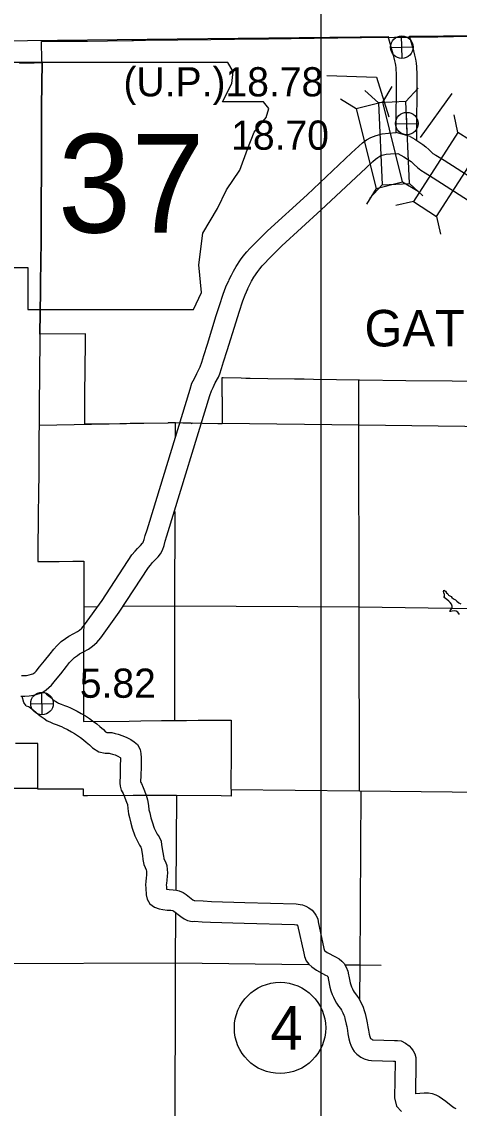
# Model space of a CAD drawing. Extents: x 77230 to 630905, y 790554 to 1662844.
# Drawn here: x 303084 to 315734, y 1607947 to 1639405 of the extents above; entities that cross this region are included whole.
import ezdxf

# ---------------------------------------------------------------- set-up
doc = ezdxf.new("R2010")
doc.units = 0
for name, color, linetype in [('Level 12', 7, 'Continuous'), ('Level 14', 7, 'Continuous'), ('Level 15', 7, 'Continuous'), ('Level 16', 7, 'Continuous'), ('Level 17', 7, 'Continuous'), ('Level 19', 7, 'Continuous'), ('Level 22', 7, 'Continuous'), ('Level 23', 7, 'Continuous'), ('Level 24', 7, 'Continuous'), ('Level 27', 7, 'Continuous'), ('Level 28', 7, 'Continuous'), ('Level 31', 7, 'Continuous'), ('Level 32', 7, 'Continuous'), ('Level 33', 7, 'Continuous'), ('Level 34', 7, 'Continuous')]:
    doc.layers.add(name, color=color, linetype=linetype)

msp = doc.modelspace()

# ---------------------------------------------------------------- linework, layer by layer
at = {"layer": 'Level 12'}
for points in [[(303674, 1638222), (303663, 1638289), (303655, 1638835), (304099, 1638839), (304988, 1638847), (305561, 1638854), (306265, 1638863), (306315, 1638864), (306659, 1638870), (307594, 1638886), (308550, 1638893), (309927, 1638906), (310220, 1638909), (311538, 1638928), (312906, 1638953), (313857, 1638959), (313926, 1638962), (313938, 1638962)], [(313938, 1638962), (314223, 1638962), (315117, 1638972), (315117, 1638973), (315568, 1638978), (316467, 1638989)], [(303015, 1638201), (303347, 1638211)], [(303347, 1638211), (303447, 1638215), (303674, 1638222)], [(303674, 1638222), (303659, 1636961), (303659, 1636870), (303659, 1636795), (303656, 1636178), (303655, 1635806), (303654, 1635691), (303654, 1635609), (303654, 1635319), (303653, 1635258), (303652, 1635080), (303652, 1635003), (303648, 1634240), (303641, 1632966), (303636, 1632540), (303635, 1632427), (303635, 1632414), (303629, 1631897), (303625, 1631611), (303609, 1630362)], [(303609, 1630362), (303625, 1631611), (303629, 1631897), (303635, 1632414), (303635, 1632427), (303636, 1632540), (303641, 1632966), (303648, 1634240), (303652, 1635003), (303652, 1635080), (303653, 1635258), (303654, 1635319), (303654, 1635609), (303654, 1635691), (303655, 1635806), (303656, 1636178), (303659, 1636795), (303659, 1636870), (303659, 1636961), (303674, 1638222)], [(303609, 1630362), (303595, 1629079), (303589, 1628427), (303584, 1627807), (303584, 1627724), (303582, 1627429), (303582, 1627400), (303581, 1627254), (303577, 1626410), (303576, 1626272), (303570, 1625818), (303557, 1625079), (303554, 1624781), (303552, 1624383), (303550, 1623773), (303556, 1623774), (304170, 1623780), (304557, 1623785), (304883, 1623789), (304880, 1623469), (304877, 1622973), (304877, 1622889), (304876, 1622469), (304875, 1622150), (304874, 1621514), (304874, 1621502), (304873, 1621446), (304873, 1621357), (304873, 1621299), (304873, 1621276), (304873, 1621266), (304873, 1621149), (304871, 1620475), (304870, 1619828), (304870, 1619144), (306192, 1619159), (306192, 1619157), (306524, 1619162), (307124, 1619171), (307514, 1619177), (307514, 1619174), (307847, 1619177), (308183, 1619180), (308518, 1619183), (308518, 1619184), (308853, 1619186), (308853, 1619183), (309142, 1619188), (309139, 1618306), (309134, 1617203), (309135, 1617152), (309143, 1617152), (309143, 1617151), (309143, 1616981), (308850, 1616989), (307559, 1616999), (306303, 1616999), (304987, 1616992), (304869, 1616991), (304870, 1617183), (303987, 1617187), (303861, 1617188), (303572, 1617189), (303548, 1617189), (303548, 1617586), (303548, 1617900), (303548, 1618225), (303547, 1618509), (303097, 1618508), (302905, 1618511)], [(318201, 1628963), (315525, 1628994), (314187, 1629010), (312850, 1629028), (311524, 1629048), (311248, 1629052), (310974, 1629056), (310195, 1629067), (309686, 1629076), (309627, 1629077), (309559, 1629078), (309427, 1629081), (308908, 1629096), (308870, 1629097), (308869, 1629097), (308869, 1629093), (308868, 1628548), (308868, 1628543), (308876, 1628542), (308877, 1627917), (308877, 1627760), (308754, 1627763), (308309, 1627773), (308009, 1627779), (308004, 1627760), (307975, 1627780), (307949, 1627784), (307947, 1627781), (307922, 1627781), (307738, 1627785), (307532, 1627790), (307314, 1627788), (307309, 1627787), (306219, 1627773), (305916, 1627768), (304904, 1627750), (304908, 1628383), (304911, 1628711), (304911, 1628866), (304914, 1629102), (304926, 1630366), (303609, 1630362)]]:
    msp.add_lwpolyline(points, dxfattribs=at)
at = {"layer": 'Level 14'}
for points in [[(314296, 1638984), (318235, 1639028), (323522, 1639077), (328068, 1639116), (330690, 1639138)], [(293947, 1638752), (297089, 1638789), (302369, 1638852), (307582, 1638906), (312865, 1638969), (313674, 1638978)]]:
    msp.add_lwpolyline(points, dxfattribs=at)
at = {"layer": 'Level 15'}
for points in [[(301883, 1617216), (302239, 1617216), (303548, 1617210)], [(309134, 1617173), (312849, 1617136), (317311, 1617093)]]:
    msp.add_lwpolyline(points, dxfattribs=at)
at = {"layer": 'Level 16'}
for points in [[(312849, 1617136), (312844, 1622477), (312834, 1627745), (312830, 1629028)], [(303600, 1627720), (306611, 1627778)], [(307516, 1627790), (307516, 1627774), (307515, 1627357)], [(308877, 1627782), (312836, 1627739), (318179, 1627668), (323444, 1627634)], [(307511, 1625228), (307505, 1622474), (307501, 1619177)], [(304876, 1622468), (305278, 1622472)], [(306029, 1622481), (307509, 1622496), (312844, 1622467), (318160, 1622388), (323421, 1622343)], [(307559, 1616999), (307538, 1614269)], [(312856, 1611101), (312866, 1612102), (312895, 1617136)], [(307533, 1613613), (307521, 1612141), (307506, 1606820)], [(294244, 1612117), (296783, 1612127), (302206, 1612135), (307527, 1612156), (311375, 1612114)], [(312444, 1612103), (312868, 1612098), (313480, 1612091)]]:
    msp.add_lwpolyline(points, dxfattribs=at)
at = {"layer": 'Level 17'}
for points in [[(315462, 1622329), (315474, 1622349), (315494, 1622380), (315511, 1622404), (315527, 1622442), (315526, 1622488), (315506, 1622540), (315471, 1622588), (315433, 1622629), (315375, 1622675), (315340, 1622708), (315302, 1622732), (315292, 1622738), (315308, 1622768), (315305, 1622822), (315291, 1622868), (315280, 1622908), (315292, 1622944), (315332, 1622916), (315363, 1622875), (315401, 1622839), (315423, 1622803), (315499, 1622760), (315524, 1622736), (315570, 1622699), (315626, 1622663), (315662, 1622626), (315719, 1622584), (315781, 1622553)], [(315744, 1622244), (315692, 1622306), (315640, 1622341), (315600, 1622349), (315532, 1622342), (315494, 1622332), (315462, 1622329)]]:
    msp.add_lwpolyline(points, dxfattribs=at)
at = {"layer": 'Level 19'}
for p, q in [((313525, 1637077), (313797, 1637529)), ((314188, 1637095), (314544, 1637485)), ((312756, 1636886), (312304, 1637159)), ((313397, 1637059), (313007, 1637415)), ((315696, 1636198), (315584, 1636714)), ((313504, 1634686), (313148, 1634296)), ((314096, 1634770), (314548, 1634498)), ((314295, 1634721), (314685, 1634365)), ((313327, 1634580), (313054, 1634128)), ((314412, 1634199), (313896, 1634087)), ((315078, 1633771), (315191, 1633255))]:
    msp.add_line(p, q, dxfattribs=at)
for points in [[(314096, 1634770), (313525, 1637077), (312756, 1636886), (313327, 1634580)], [(313397, 1637059), (313504, 1634686), (314295, 1634721), (314188, 1637095)], [(315078, 1633771), (316363, 1635770), (315696, 1636198), (314412, 1634199)]]:
    msp.add_lwpolyline(points, close=True, dxfattribs=at)
at = {"layer": 'Level 22'}
for points in [[(313911, 1636194), (313916, 1637858), (313905, 1638071), (313901, 1638143), (313893, 1638195), (313871, 1638277), (313838, 1638400), (313674, 1638978)], [(314510, 1635963), (314516, 1637873), (314504, 1638103), (314498, 1638204), (314481, 1638319), (314450, 1638433), (314417, 1638559), (314296, 1638984)], [(303207, 1619603), (303142, 1619697), (303092, 1619871)], [(303712, 1620010), (303803, 1619937), (303890, 1619865), (303984, 1619783), (304070, 1619724), (304113, 1619695), (304147, 1619680), (304221, 1619647), (304318, 1619611), (304410, 1619577), (304489, 1619539), (304571, 1619500), (304685, 1619441), (304805, 1619377), (304926, 1619313), (305038, 1619234), (305134, 1619168), (305251, 1619080), (305338, 1619001), (305450, 1618913), (305510, 1618850), (305544, 1618829), (305564, 1618824), (305685, 1618825), (305783, 1618801), (305874, 1618780), (306010, 1618732), (306126, 1618678), (306239, 1618619), (306330, 1618555), (306429, 1618476), (306503, 1618336), (306531, 1618215), (306541, 1618092), (306532, 1617830), (306526, 1617585), (306522, 1617401), (306525, 1617379), (306547, 1617345), (306592, 1617238), (306680, 1617008), (306723, 1616879), (306748, 1616708), (306763, 1616584), (306784, 1616500), (306816, 1616355), (306852, 1616238), (306912, 1616061), (306968, 1615944), (306997, 1615885), (307056, 1615808), (307113, 1615678), (307125, 1615571), (307165, 1615353), (307179, 1615243), (307190, 1615186), (307196, 1615173), (307244, 1615078), (307276, 1614973), (307289, 1614863), (307294, 1614760), (307290, 1614664), (307282, 1614552), (307267, 1614450), (307264, 1614414), (307269, 1614354), (307272, 1614292), (307350, 1614282), (307465, 1614275), (307561, 1614259), (307637, 1614242), (307748, 1614196), (307837, 1614137), (308032, 1613982), (308066, 1613960), (308084, 1613961), (308334, 1613948), (308568, 1613937), (309532, 1613908)], [(303207, 1619603), (303283, 1619577), (303298, 1619571), (303333, 1619544), (303425, 1619471), (303503, 1619407), (303614, 1619310), (303733, 1619227), (303822, 1619169), (303900, 1619133), (303994, 1619091), (304110, 1619048), (304177, 1619023), (304230, 1618998), (304305, 1618962), (304407, 1618910), (304523, 1618848), (304611, 1618801), (304695, 1618742), (304784, 1618681), (304867, 1618618), (304950, 1618542), (305046, 1618467), (305130, 1618379), (305309, 1618269), (305493, 1618224), (305615, 1618225), (305645, 1618217), (305707, 1618203), (305782, 1618177), (305858, 1618141), (305926, 1618105), (305938, 1618096), (305940, 1618078), (305932, 1617847), (305926, 1617599), (305921, 1617363), (305934, 1617276), (305956, 1617153), (306015, 1617063), (306035, 1617015), (306114, 1616806), (306137, 1616739), (306153, 1616627), (306172, 1616474), (306200, 1616363), (306235, 1616203), (306281, 1616053), (306356, 1615834), (306429, 1615681), (306485, 1615568), (306528, 1615511), (306532, 1615483), (306572, 1615261), (306587, 1615147), (306613, 1615009), (306652, 1614918), (306685, 1614853), (306686, 1614850), (306690, 1614812), (306694, 1614756), (306691, 1614700), (306685, 1614619), (306670, 1614517), (306662, 1614412), (306670, 1614316), (306678, 1614125), (306707, 1614003), (306785, 1613869), (306921, 1613768), (307053, 1613724), (307166, 1613700), (307293, 1613685), (307397, 1613678), (307445, 1613670), (307453, 1613668), (307466, 1613663), (307485, 1613650), (307680, 1613496), (307781, 1613429), (307881, 1613382), (308016, 1613357), (308083, 1613360), (308305, 1613348), (308546, 1613338), (309514, 1613308)], [(309531, 1613908), (311020, 1613866), (311134, 1613850), (311205, 1613834), (311295, 1613802), (311385, 1613753), (311481, 1613680), (311548, 1613598), (311587, 1613540), (311643, 1613433), (311652, 1613345), (311823, 1612569), (311835, 1612519), (311847, 1612508), (311915, 1612461), (312155, 1612332), (312263, 1612271), (312334, 1612208), (312409, 1612134), (312467, 1612033), (312517, 1611915), (312536, 1611814), (312543, 1611770), (312581, 1611583), (312596, 1611524), (312618, 1611465), (312644, 1611402), (312665, 1611358), (312692, 1611313), (312733, 1611256), (312781, 1611189), (312838, 1611112), (312880, 1611033), (312915, 1610956), (312951, 1610874), (312986, 1610780), (313010, 1610687), (313050, 1610513), (313069, 1610423), (313090, 1610300), (313107, 1610204), (313127, 1610096), (313146, 1610026), (313158, 1609991), (313168, 1609968), (313168, 1609968), (313170, 1609966), (313203, 1609943), (313225, 1609931), (313243, 1609925), (313244, 1609925), (313864, 1609913), (313944, 1609907), (314058, 1609896), (314184, 1609834), (314290, 1609759), (314352, 1609678), (314404, 1609611), (314448, 1609519), (314475, 1609419), (314483, 1609319), (314482, 1609282)], [(309514, 1613308), (310971, 1613267), (311025, 1613260), (311037, 1613257), (311048, 1613253), (311058, 1613248), (311059, 1613247), (311238, 1612434), (311261, 1612341), (311303, 1612217), (311388, 1612115), (311473, 1612037), (311602, 1611948), (311866, 1611805), (311914, 1611779), (311924, 1611770), (311928, 1611766), (311939, 1611741), (311945, 1611706), (311954, 1611658), (311995, 1611453), (312022, 1611344), (312061, 1611243), (312096, 1611159), (312135, 1611075), (312189, 1610985), (312245, 1610906), (312297, 1610834), (312329, 1610791), (312340, 1610770), (312366, 1610712), (312395, 1610647), (312413, 1610600), (312426, 1610546), (312464, 1610385), (312479, 1610311), (312499, 1610197), (312516, 1610098), (312542, 1609961), (312572, 1609852), (312597, 1609775), (312644, 1609670), (312700, 1609591), (312771, 1609513), (312890, 1609430), (312988, 1609378), (313110, 1609337), (313201, 1609326), (313834, 1609314), (313877, 1609310), (313882, 1609304), (313882, 1609299)], [(313882, 1609295), (313866, 1608251)], [(314482, 1609286), (314468, 1608369)], [(313866, 1608251), (313917, 1608003), (314060, 1607855)], [(314477, 1608377), (314593, 1608387), (314723, 1608395), (314841, 1608391), (314954, 1608378), (315061, 1608340), (315153, 1608288), (315343, 1608154), (315549, 1607991), (315601, 1607956), (315631, 1607941)]]:
    msp.add_lwpolyline(points, dxfattribs=at)
at = {"layer": 'Level 23'}
for points in [[(309072, 1631920), (309144, 1632071), (309210, 1632187), (309286, 1632321), (309412, 1632509), (309488, 1632618), (309590, 1632741), (309680, 1632835), (309781, 1632946), (310015, 1633180), (310188, 1633354), (311333, 1634398), (312619, 1635607), (312829, 1635804), (312935, 1635900), (313053, 1635982), (313177, 1636054), (313327, 1636113), (313501, 1636156), (313686, 1636183), (313911, 1636194)], [(314310, 1636085), (313911, 1636194)], [(314310, 1636085), (314445, 1636001), (314681, 1635853), (314769, 1635786), (314851, 1635703), (314922, 1635636), (314974, 1635593), (315058, 1635541), (315294, 1635401), (317823, 1633776)], [(309614, 1631663), (309676, 1631793), (309731, 1631890), (309797, 1632005), (309908, 1632171), (309966, 1632255), (310038, 1632341), (310118, 1632425), (310215, 1632531), (310440, 1632757), (310603, 1632921), (311741, 1633958), (313030, 1635169), (313236, 1635363), (313309, 1635429), (313376, 1635476), (313440, 1635513), (313509, 1635540), (313617, 1635567), (313743, 1635585), (313960, 1635595)], [(313960, 1635595), (314128, 1635492), (314340, 1635359), (314372, 1635334), (314431, 1635274), (314525, 1635186), (314622, 1635106), (314746, 1635028), (314979, 1634890), (317479, 1633284)], [(303078, 1620474), (303142, 1620475), (303223, 1620481), (303300, 1620495), (303362, 1620513), (303408, 1620526), (303437, 1620545), (303464, 1620567), (303499, 1620603), (303601, 1620724), (303746, 1620899), (303903, 1621106), (304008, 1621241), (304100, 1621340), (304220, 1621460), (304348, 1621551), (304448, 1621619), (304586, 1621693), (304698, 1621753), (304755, 1621793), (304820, 1621852), (304897, 1621942), (305410, 1622649), (306265, 1623969), (306360, 1624077), (306432, 1624155), (306513, 1624240), (306576, 1624310), (306596, 1624332), (306599, 1624339), (306628, 1624418), (306657, 1624527), (306708, 1624696), (306749, 1624823), (307953, 1628763), (308006, 1628939), (308075, 1629080), (308145, 1629225), (308226, 1629371), (308241, 1629411), (308287, 1629550), (308347, 1629743), (308450, 1630068), (308707, 1630899), (308801, 1631186), (308909, 1631521), (308987, 1631728), (309069, 1631913)], [(303054, 1619874), (303169, 1619875), (303300, 1619886), (303434, 1619909), (303531, 1619937), (303661, 1619976), (303791, 1620059), (303870, 1620125), (303942, 1620198), (304061, 1620339), (304217, 1620526), (304380, 1620742), (304465, 1620852), (304531, 1620923), (304609, 1621000), (304691, 1621059), (304758, 1621104), (304870, 1621164), (305013, 1621241), (305130, 1621323), (305251, 1621433), (305368, 1621569), (305905, 1622310), (306746, 1623607), (306806, 1623676), (306868, 1623744), (306953, 1623832), (307025, 1623911), (307100, 1623998), (307152, 1624103), (307201, 1624238), (307234, 1624364), (307280, 1624517), (307321, 1624643), (308526, 1628588), (308566, 1628718), (308615, 1628818), (308679, 1628949), (308771, 1629117), (308807, 1629209), (308859, 1629367), (308919, 1629563), (309023, 1629888), (309279, 1630717), (309372, 1631001), (309475, 1631324), (309542, 1631501), (309617, 1631670)]]:
    msp.add_lwpolyline(points, dxfattribs=at)
at = {"layer": 'Level 24'}
msp.add_lwpolyline([(302192, 1638228), (302534, 1635944), (302382, 1632480), (302687, 1632289), (303258, 1632289), (303258, 1631071), (308054, 1631071), (308282, 1631566), (308206, 1632366), (308320, 1633279), (308739, 1634002), (309006, 1634535), (309386, 1635106), (309615, 1635715), (309805, 1636210), (310147, 1636629), (310224, 1636895), (310071, 1637086), (308891, 1637086), (309158, 1637619), (309196, 1637961), (309038, 1638224)], close=True, dxfattribs=at)
at = {"layer": 'Level 28'}
msp.add_line((311736, 1658884), (311736, 1488604), dxfattribs=at)
at = {"layer": 'Level 31'}
msp.add_line((314611, 1636055), (315526, 1637328), dxfattribs=at)
at = {"layer": 'Level 32'}
for p, q in [((311905, 1637845), (313337, 1637805)), ((313337, 1637805), (313696, 1636652))]:
    msp.add_line(p, q, dxfattribs=at)
at = {"layer": 'Level 33'}
msp.add_circle((310552, 1610273), 1320, dxfattribs=at)
at = {"layer": 'Level 34'}
for p, q in [((314080, 1638346), (314065, 1638997)), ((313747, 1638664), (314398, 1638679)), ((314227, 1636130), (314212, 1636781)), ((313894, 1636448), (314545, 1636463)), ((303677, 1619337), (303662, 1619988)), ((303344, 1619655), (303995, 1619670))]:
    msp.add_line(p, q, dxfattribs=at)
for centre in [(314073, 1638671), (314220, 1636456), (303669, 1619663)]:
    msp.add_circle(centre, 326, dxfattribs=at)

# ---------------------------------------------------------------- texts
at = {"layer": 'Level 24'}
msp.add_text('37', height=2851.2, dxfattribs=at).set_placement((304127, 1633302))
at = {"layer": 'Level 27'}
msp.add_text('GATEWAY', height=1056, dxfattribs=at).set_placement((312994, 1630005))
at = {"layer": 'Level 31'}
msp.add_text('5.82', height=844.8, dxfattribs=at).set_placement((304763, 1619832))
at = {"layer": 'Level 32'}
for s, p in [('(U.P.)18.78', (306025, 1637244)), ('18.70', (309139, 1635700))]:
    msp.add_text(s, height=844.8, dxfattribs=at).set_placement(p)
at = {"layer": 'Level 33'}
msp.add_text('4', height=1267, dxfattribs=at).set_placement((310269, 1609639))

doc.saveas('drawing.dxf')
